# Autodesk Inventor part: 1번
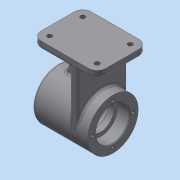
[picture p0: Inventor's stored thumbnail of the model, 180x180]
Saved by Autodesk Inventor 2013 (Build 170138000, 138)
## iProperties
Created: 2019-03
Part Number: 1번
Material: 일반
Document SubType Name: Modeling
Designer: dgall
Density: 7.85 g/cm^3
Mass: 2147.68 g
Surface Area: 603.786 cm^2
Volume: 273.59 cm^3
Author: dgall
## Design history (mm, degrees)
sketch "스케치1"
  geometry: L1 (0, 0)-(90, 0); L2 (90, 0)-(90, 70); L3 (90, 70)-(0, 70); L4 (0, 70)-(0, 0)
  constraints: 8 end point, 2 parallel, 1 horizontal, 1 perpendicular
  dimensions: "d0" = 90 distance of L2.end L3.end; "d2" = 70 distance of L1.end L2.end
extrude "돌출1" new body sketch "스케치1" distance "d3" = 10; taper "d4" = 0 deg
node "작업 평면1"
sketch "스케치2"
  geometry: L1 (90, 10)-(90, 0) reference; L2 (90, 0)-(0, 0) reference; L3 (0, 0)-(0, 10) reference; L4 (0, 10)-(90, 10) reference; L5 (77, -75)-(0, -75); L6 (0, -75)-(0, -110); L7 (0, -110)-(77, -110); L8 (77, -110)-(77, -98.5); L9 (77, -98.5)-(60, -98.5); L10 (60, -98.5)-(60, -93); L11 (60, -93)-(52, -93); L12 (52, -93)-(52, -102.5); L13 (52, -102.5)-(20, -102.5); L14 (20, -102.5)-(20, -92.5); L15 (20, -92.5)-(9, -92.5); L16 (9, -92.5)-(9, -88.5); L17 (9, -88.5)-(6, -88.5); L18 (6, -88.5)-(6, -75)
  constraints: 28 end point, 11 parallel, 3 perpendicular, 2 vertical alignment, 1 point on line, 1 vertical
  dimensions: "d5" = 77 distance of L6.end L7.end; "d7" = 85 distance between parallel lines of L4 L5; "d8" = 47 diameter of L9 L5; "d9" = 36 diameter of L11 L5; "d10" = 55 diameter of L13 L5; "d11" = 35 diameter of L15 L5; "d12" = 27 diameter of L17 L5; "d13" = 17 distance of L8.end L9.end; "d14" = 8 distance of L10.end L11.end; "d15" = 32 distance of L12.end L13.end; "d16" = 11 distance of L14.end L15.end; "d17" = 3 distance of L16.end L17.end; "d18" = 70 diameter of L7 L5
revolve "회전1" sketch "스케치2" stored, may be unused: angle "d19" = 90 deg
node "작업 평면2"
sketch "스케치3"
  geometry: L1 (0, 0)-(-10, 0) reference; L2 (-10, 0)-(-10, 70) reference; L3 (-10, 70)-(0, 70) reference; L4 (0, 70)-(0, 0) reference; L5 (75, 70)-(0, 70); L6 (75, 0)-(0, 0); L7 (0, 70)-(0, 0) reference; C1 r 23.5 at (75, 35) reference; C2 r 35 at (75, 35) reference; A1 r 35 centre (75, 35) between (75, 70) and (75, 0) reference
  constraints: 4 end point, 3 tangent, 2 perpendicular, 2 point on circle
extrude "돌출2" join sketch "스케치3" distance "d21" = 10; taper "d22" = 0 deg
sketch "스케치4"
  geometry: L1 (90, 10)-(90, 0) reference; L2 (90, 0)-(62, 0) reference; L3 (62, 0)-(62, -40) reference; L4 (62, -40)-(77, -40) reference; L5 (77, -40)-(77, -51.5) reference; L6 (77, -51.5)-(60, -51.5) reference; L7 (60, -51.5)-(60, -57) reference; L8 (60, -57)-(52, -57) reference; L9 (52, -57)-(52, -47.5) reference; L10 (52, -47.5)-(20, -47.5) reference; L11 (20, -47.5)-(20, -57.5) reference; L12 (20, -57.5)-(9, -57.5) reference; L13 (9, -57.5)-(9, -61.5) reference; L14 (9, -61.5)-(6, -61.5) reference; L15 (6, -61.5)-(6, -88.5) reference; L16 (6, -88.5)-(9, -88.5) reference; L17 (9, -88.5)-(9, -92.5) reference; L18 (9, -92.5)-(20, -92.5) reference; L19 (20, -92.5)-(20, -102.5) reference; L20 (20, -102.5)-(52, -102.5) reference; L21 (52, -102.5)-(52, -93) reference; L22 (52, -93)-(60, -93) reference; L23 (60, -93)-(60, -98.5) reference; L24 (60, -98.5)-(77, -98.5) reference; L25 (77, -98.5)-(77, -110) reference; L26 (77, -110)-(0, -110) reference; L27 (0, -110)-(0, -40) reference; L28 (0, -40)-(52, -40) reference; L29 (52, -40)-(52, 0) reference; L30 (52, 0)-(0, 0) reference; L31 (0, 0)-(0, 10) reference; L32 (0, 10)-(90, 10) reference; L33 (30, 0)-(15.441, -40)
  constraints: 2 end point, 1 point on line
  dimensions: "d26" = 70 deg angle of L30 L33; "d27" = 21.99996 distance from line of L29 L33.start; "d28" = 36.55877 distance from line of L29 L33.end
feature "리브1" sketch "스케치4" dims "d29" = 1, "d30" = 10, "d31" = 0, "d32" = 0, "d33" = 1, "d34" = 1
fillet "모깎기1" dims "d35" = 12
sketch "스케치5"
  geometry: L1 (-62, 0)-(-62, 70) reference; L2 (-78, 70)-(-62, 70) reference; L3 (-90, 12)-(-90, 58) reference; L4 (-62, 0)-(-78, 0) reference; L5 (-52, 0)-(-62, 0) reference; L6 (-52, 30)-(-52, 0) reference; L7 (-30, 30)-(-52, 30) reference; L8 (-30, 40)-(-30, 30) reference; L9 (-52, 40)-(-30, 40) reference; L10 (-52, 70)-(-52, 40) reference; L11 (-52, 70)-(-12, 70) reference; L12 (0, 58)-(0, 12) reference; L13 (-12, 0)-(-52, 0) reference; L14 (-62, 70)-(-52, 70) reference; A1 r 12 centre (-78, 12) between (-90, 12) and (-78, 0) reference; A2 r 12 centre (-78, 58) between (-78, 70) and (-90, 58) reference; A3 r 12 centre (-78, 58) between (-78, 70) and (-90, 58) reference; A4 r 12 centre (-78, 12) between (-90, 12) and (-78, 0) reference; A5 r 12 centre (-12, 58) between (0, 58) and (-12, 70) reference; A6 r 12 centre (-12, 12) between (-12, 0) and (0, 12) reference; 1 further point
hole "구멍1" sketch "스케치5" at (-12, 12), (-78, 12), (-78, 58), (-12, 58) diameter "d36" = 6.6; stored, may be unused: countersink angle "d40" = 90 deg, drill point angle "d42" = 118 deg; dims "d37" = 6, "d38" = 16, "d39" = 2, "d41" = 8
sketch "스케치6" dims "d43" = 56
  geometry: C1 r 35 at (0, 0) reference; C2 r 23.5 at (0, 0) reference; 3 further points
  constraints: 2 vertical alignment, 1 coincident, 2 other
hole "구멍2" sketch "스케치6" at (0, 28) diameter "d45" = 4.134; stored, may be unused: countersink angle "d49" = 90 deg, drill point angle "d51" = 118 deg; dims "d46" = 11, "d47" = 16, "d48" = 2, "d50" = 14
chamfer "모따기1" distance "d55" = 1; stored, may be unused: second distance "d56" = 2, angle "d57" = 45 deg
fillet "모깎기2" dims "d58" = 3
fillet "모깎기3" dims "d59" = 3
fillet "모깎기4" dims "d60" = 3
fillet "모깎기5" dims "d61" = 3
node "솔리드1"
pattern_circular "원형 패턴1" dims angle "d53" = 360 deg
node "절단 모서리 투영1"
node "절단 모서리 투영2"
node "절단 모서리 투영3"
node "절단 모서리 투영4"
other parameters: "d20" = -28
